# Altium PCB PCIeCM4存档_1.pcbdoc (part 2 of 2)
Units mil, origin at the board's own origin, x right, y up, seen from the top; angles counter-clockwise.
Board outline 9275 x 6345 mil, 4 copper layers (Top Layer, GND, 3V3, Bottom Layer); 98 components, 111 nets, 637 pads, 303 vias.
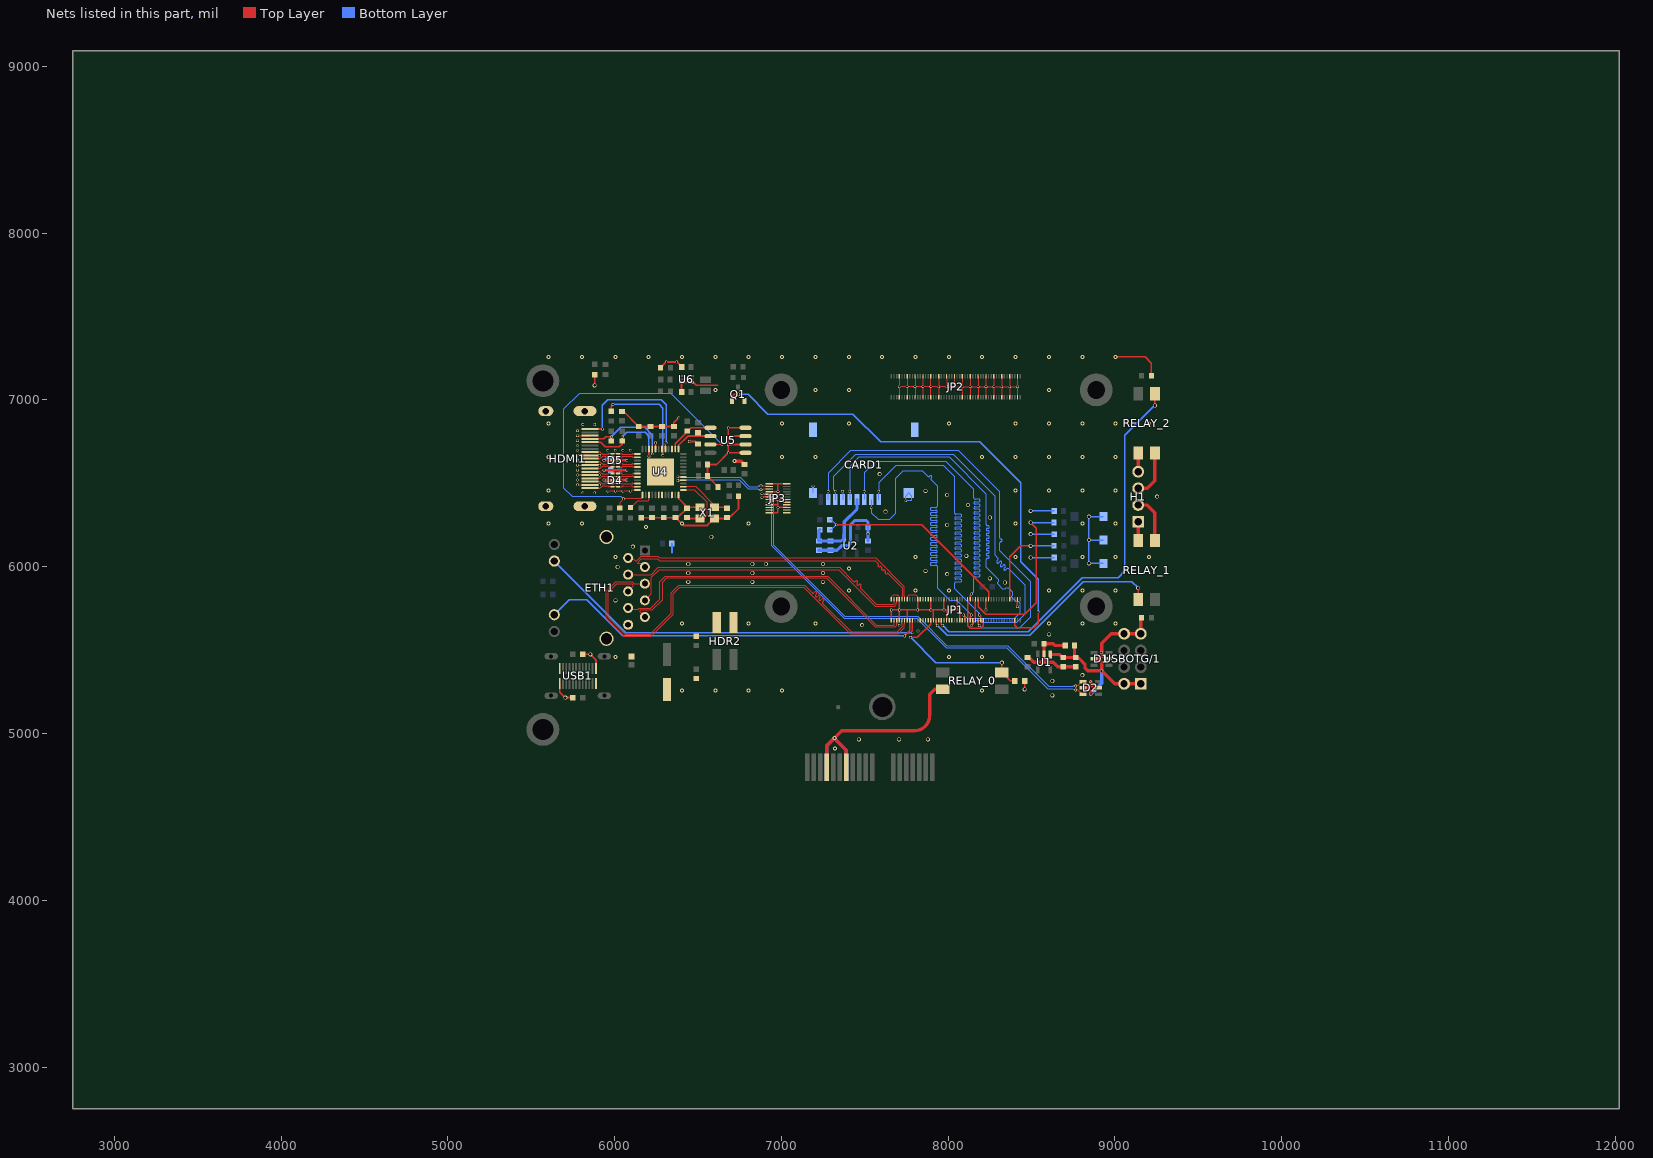
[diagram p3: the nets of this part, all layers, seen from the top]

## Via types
v1: diameter 15.7, hole 11.8, Top Layer to Bottom Layer, 94 vias
v2: diameter 24, hole 12, Top Layer to Bottom Layer, 92 vias
v3: diameter 24, hole 16, Top Layer to Bottom Layer, 67 vias
v4: diameter 15.75, hole 11.81, Top Layer to Bottom Layer, 49 vias
v5: diameter 15.75, hole 11.8, Top Layer to Bottom Layer, 1 vias

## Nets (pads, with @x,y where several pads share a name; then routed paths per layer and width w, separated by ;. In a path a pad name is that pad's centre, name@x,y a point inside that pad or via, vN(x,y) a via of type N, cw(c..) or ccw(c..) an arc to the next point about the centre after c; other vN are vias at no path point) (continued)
GND: BOOT.2 C1.2 C2.1 C3.1 C4.1 C5.1 C6.1 C7.2 C8.1 C9.2 C10.2 C11.1 C12.1 C13.1 C14.1 C15.1 C16.1 C17.1 C18.1 C19.1 C20.1 C21.1 C22.2 C23.1 C24.2 C25.1 C26.1 C27.1 C28.1 C30.1 C31.1 C32.2 C33.2 C34.2 C35.1 CARD1.6 CARD1.10 CARD1.11 CARD1.12 CARD1.13 D1.2 D2.2 D3.2 D4.3 D4.8 D5.3 D5.8 ETH1.P10 ETH1.SHIELD0 ETH1.SHIELD1 HDMI1.2 HDMI1.5 HDMI1.8 HDMI1.11 HDMI1.17 HDMI1.20 HDMI1.21 HDMI1.22 HDMI1.23 HDR2.2 HDR2.4 JP1.15 JP1.18 JP1.21 JP1.24 JP1.29 JP1.34 JP1.39 JP1.44 JP1.47 JP1.50 JP1.51 JP1.54 JP1.57 JP1.61 JP1.66 JP1.71 JP1.76 JP1.80 JP1.83 JP1.87 JP1.99 JP2.2 JP2.5 JP2.8 JP2.11 JP2.14 JP2.17 JP2.20 JP2.23 JP2.32 JP2.35 JP2.38 JP2.41 JP2.44 JP2.47 JP2.54 JP2.57 JP2.60 JP2.63 JP2.66 JP2.69 JP2.72 JP2.75 JP2.78 JP2.81 JP2.84 JP2.87 JP2.90 JP2.93 JP2.96 JP2.99 JP3.1 JP3.6 JP3.7 JP3.11 JP3.12 JP3.17 JP3.23 JP3.24 PWR.1 Q1.2 R3.1 R4.1 R9.1 R12.1 R15.2 R16.1 R18.1 R22.2 R27.1 R28.1 RECOVERY.2 RESET.2 U1.2 U2.2 U4.15 U4.20 U4.36 U4.42 U4.43 U4.46 U4.48 U4.49 U5.1 U5.2 U5.3 U5.4 U6.1 U6.6 USB1.A1 USB1.A12 USB1.B1 USB1.B12 USBOTG/1.7 USBOTG/1.8 X1.2 X1.4 | length 12697.8
  Top Layer w4.9: v4(5777.28,6490.6) HDMI1.2@5852.28,6490.6 ; v4(5777.28,6549.66) HDMI1.5@5852.28,6549.66 ; v4(5777.28,6608.71) HDMI1.8@5852.28,6608.71 ; v4(5777.28,6667.77) HDMI1.11@5852.28,6667.77 ; v4(5777.28,6785.88) HDMI1.17@5852.28,6785.88 ; JP1.51@7659.82,5803.77 7659.82,5820.12 7669.82,5830.12 7697.06,5830.12 7707.06,5820.12 JP1.54@7707.06,5803.77 ; JP1.57@7754.31,5803.77 7754.31,5820.12 7764.31,5830.12 7807.3,5830.12 7817.3,5820.12 JP1.61@7817.3,5803.77
  Top Layer w5.4: v4(5960,6453.08) v1(6095,6453.08) 6101.73,6459.82 U4.36@6137.2,6459.82 ; JP2.47@7707.06,7016.4 JP2.54@7707.06,7142.38 ; v1(7707.06,7079.39) v1(7990.53,7079.39) ; JP2.44@7754.31,7016.4 JP2.57@7754.31,7142.38 ; JP2.41@7801.55,7016.4 JP2.60@7801.55,7142.38 ; JP2.38@7848.79,7016.4 JP2.63@7848.79,7142.38 ; JP2.35@7896.04,7016.4 JP2.66@7896.04,7142.38 ; JP2.32@7943.28,7016.4 JP2.69@7943.28,7142.38 ; JP2.72@7990.53,7142.38 v1(7990.53,7079.39) ; v1(8037.77,7079.39) JP2.75@8037.77,7142.38 ; JP2.23@8085.01,7016.4 JP2.78@8085.01,7142.38 ; JP2.20@8132.26,7016.4 JP2.81@8132.26,7142.38 ; JP2.17@8179.5,7016.4 JP2.84@8179.5,7142.38 ; JP2.14@8226.75,7016.4 JP2.87@8226.75,7142.38 ; JP2.11@8273.99,7016.4 JP2.90@8273.99,7142.38 ; JP2.8@8321.23,7016.4 JP2.93@8321.23,7142.38 ; JP2.5@8368.48,7016.4 JP2.96@8368.48,7142.38 ; JP2.2@8415.72,7016.4 JP2.99@8415.72,7142.38 ; v1(8415.72,7079.39) v1(7990.53,7079.39)
  Top Layer w7.9: v3(5880.74,7087.9) 5880.87,7088.03 PWR.1@5880.87,7151.1 ; JP3.1@6927.65,6323.82 6979.62,6323.82 6979.62,6497.05 ; JP3.7@6927.66,6371.06 6979.62,6371.06 ; JP3.11@6927.65,6402.56 v1(6979.62,6402.56) JP3.12@7031.59,6402.56 ; JP3.17@6927.66,6449.8 v1(6979.66,6449.8) ; JP3.23@6927.65,6497.05 JP3.24@7031.59,6497.05 ; v1(6979.62,6355.32) JP3.6@7031.59,6355.32 ; JP1.50@7659.82,5677.79 v1(7659.82,5740.78) v1(8069.27,5740.6) ; JP1.47@7707.06,5677.79 JP1.54@7707.06,5803.77 ; JP1.44@7754.31,5677.79 7754.31,5740.78 ; v1(7817.3,5740.78) JP1.61@7817.3,5803.77 ; v1(7896.04,5740.78) JP1.66@7896.04,5803.77 ; JP1.34@7911.79,5677.79 7911.79,5740.78 ; v1(7974.78,5740.78) JP1.71@7974.78,5803.77 ; JP1.29@7990.53,5677.79 7990.53,5740.78 ; 8053.52,5740.78 JP1.76@8053.52,5803.77 ; JP1.24@8069.27,5677.79 v1@8069.27,5740.78 ; JP1.21@8116.41,5677.97 8116.41,5646.37 8132.76,5630.02 8194.75,5630.02 8210.9,5646.16 JP1.15@8210.9,5677.97 ; JP1.21@8116.51,5677.79 8116.51,5740.78 JP1.80@8116.51,5803.77 ; JP1.18@8163.75,5677.79 8163.75,5740.78 JP1.83@8163.75,5803.77 ; v1(8226.75,5740.78) JP1.87@8226.75,5803.77 ; v1(8415.72,5760.78) JP1.99@8415.72,5808.77 ; v3(8459.08,5265) R28.1@8459.08,5315 ; v2@9009.35,7258.33 9181.09,7258.33 9219.08,7220.34 R4.1@9219.08,7145
  Top Layer w11: USB1.A12@5671.19,5300.2 5671.19,5248.23 v3(5704.42,5215) R16.1@5749.76,5215 ; R15.2@5809.08,5475 v3(5854.42,5475) 5887.65,5441.77 USB1.B12@5887.65,5389.8 ; C27.1@6045,6930.64 6055,6930.64 C16.1@6145,6840.64 C20.1@6355,6840.64 6355,6863.08 v1(6385,6893.08) ; R22.2@6160,6293.42 6362.9,6293.42 C18.1@6365,6295.52 ; U4.20@6245.47,6705.88 v4(6245.47,6743.08) ; U4.48@6383.27,6430.29 6383.27,6409.68 6435,6357.95 C22.2@6435,6350.64 ; v1(6448.31,6750.61) 6485.03,6750.61 C28.1@6500,6735.64 ; X1.4@6511.69,6356.55 6440.9,6356.55 C22.2@6435,6350.64 ; R18.1@6624.66,6478.08 6622.56,6478.08 C26.1@6557.56,6543.08 C25.1@6557.56,6613.08 6611.68,6613.08 v1(6681.68,6683.08) ; C24.2@6675,6295.52 6669.1,6289.62 X1.2@6598.31,6289.62 ; v1(6681.68,6733.08) U5.2@6785.61,6733.08 ; v1(6681.68,6783.08) U5.3@6785.61,6783.08 ; C23.1@6742.88,6422.77 6742.88,6348.4 6684.1,6289.62 X1.2@6598.31,6289.62 ; U5.1@6785.61,6683.08 v1(6681.68,6683.08) ; U5.4@6785.61,6833.08 v1(6681.68,6833.08) v1(6681.68,6683.08) ; C18.1@6365,6295.52 6379.88,6295.52 C22.2@6435,6350.64 ; C18.1@6365,6295.52 6412.52,6248 6556.69,6248 X1.2@6598.31,6289.62
  Top Layer w11.8: R27.1@6275.34,7193.08 v1(6310.34,7228.08) v1(6372.44,7228.08) C31.1@6402.44,7198.08 ; C30.1@6401.46,7049.06 U6.6@6401.46,7103.4 6473.54,7103.4 6488.85,7088.08 6616.62,7088.08
  Top Layer w15.7: v4(5936.8,6519.98) v4(6073.2,6520.13) ; v4(5936.8,6579.18) v4(6073.2,6579.18) ; v4(5936.8,6638.09) v4(6073.2,6638.24)
  Top Layer w19.3: C5.1@8480,5460.64 8513.54,5427.11 8597.3,5427.11 ; C3.1@8702.44,5528.08 8639.77,5528.08 8629.77,5538.08 8575,5538.08 U1.2@8575,5473.5 8575,5427.11 8630.42,5427.11 8656.83,5400.7 8754.83,5400.7 C4.1@8755,5400.52
  Top Layer w20: v2(6719.42,6632.56) 6759.42,6632.56 C35.1@6779.42,6612.56 ; USBOTG/1.7@9155,5598.08 9155,5690.24 R3.1@9159.76,5695
  Top Layer w20.9: v1(8855,5310.48) 8855,5295.67 8877.59,5273.08 D2.2@8900.24,5273.08 ; D1.2@8965.24,5448.08 8942.59,5448.08 8920,5470.67 v1(8920,5485.48) 8920,5540.23 8977.85,5598.08 USBOTG/1.7@9155,5598.08
  Bottom Layer w5.4: CARD1.10@7189.28,6442.26 CARD1.10@7189.5,6442.48 v1(7189.5,6483.47) ; v1(7744.62,6396.77) 7782.78,6396.77 7782.78,6424.02 CARD1.13@7764.31,6442.48 7744.62,6422.79 v1(7744.62,6396.77)
  Bottom Layer w6.2: CARD1.6@7366.67,6403.11 v1(7366.67,6451.77)
  Bottom Layer w7.9: v3(8494.76,6055) C32.2@8636.86,6055 ; v3(8494.76,6194.99) C34.2@8636.86,6195 ; v3(8494.76,6335) C33.2@8636.86,6335 ; BOOT.2@8930.44,6020 v3(8844.42,6020) v3(8844.42,6160) ; RESET.2@8930.44,6160 v3(8844.42,6160) ; RECOVERY.2@8930.44,6300 v3(8844.42,6300) v3(8844.42,6160)
  Bottom Layer w10: C11.1@6341.98,6140 6344.35,6137.63 6344.35,6083.33
  Bottom Layer w11: v4(5936.8,6519.98) 5947.6,6509.18 C13.1@5977.44,6509.18 ; v4(5936.8,6579.18) C17.1@5977.44,6579.18 ; v4(5936.8,6638.09) 5947.89,6649.18 C12.1@5977.44,6649.18
  Bottom Layer w19.3: C7.2@7224.62,6099.21 7333.35,6099.21 7361.22,6127.08 7400.86,6127.08 7414.62,6140.84 U2.2@7414.62,6172.19 7414.62,6251.77 7439.96,6277.11 7509.28,6277.11 7519.28,6267.11 7519.28,6154.67 C8.1@7519.62,6154.33
  other v1: 7819.42,5615 7706.96,5649.04 7707.06,5740.78 7519.28,6197.53 5810,6443.08 5880,6443.08 6005,6453.08 6050,6453.08 5810,6853.08 5880,6853.08 7754.31,7079.39 7801.55,7079.39 7848.8,7079.39 7896.04,7079.39 7943.28,7079.39 8085.01,7079.39 8132.26,7079.39 8179.5,7079.39 8226.75,7079.39 8273.99,7079.39 8321.23,7079.39 8368.48,7079.39
  other v2: 7322.45,4911.21 6404.4,5258.38 6604.4,5258.38 6804.4,5258.38 7004.4,5258.38 8204.4,5258.38 6004.4,5458.38 8004.4,5458.38 8204.4,5458.38 6404.4,5658.38 6804.4,5658.38 7204.4,5658.38 8604.4,5658.38 8804.4,5658.38 9004.4,5658.38 7404.4,5858.38 7804.4,5858.38 8004.4,5858.38 8604.4,5858.38 8804.4,5858.38 9004.4,5858.38 7406.15,5990.03 6004.4,6058.38 7804.4,6058.38 8404.4,6058.38 8804.4,6058.38 9004.4,6058.38 9204.4,6058.38 6189.4,6238.38 5604.4,6258.38 5804.4,6258.38 6404.4,6258.38 6804.4,6258.38 8404.4,6258.38 8804.4,6258.38 9004.4,6258.38 5604.4,6458.38 8404.4,6458.38 8604.4,6458.38 8804.4,6458.38 9004.4,6458.38 5604.4,6658.38 7004.4,6658.38 7204.4,6658.38 8204.4,6658.38 8404.4,6658.38 8604.4,6658.38 8804.4,6658.38 9004.4,6658.38 5604.4,6858.38 7004.4,6858.38 7404.4,6858.38 8004.4,6858.38 8404.4,6858.38 8604.4,6858.38 8804.4,6858.38 9004.4,6858.38 9204.4,6858.38 6604.4,7058.38 7204.4,7058.38 7404.4,7058.38 8604.4,7058.38 5604.4,7258.38 5804.4,7258.38 6004.4,7258.38 6204.4,7258.38 6404.4,7258.38 6604.4,7258.38 6804.4,7258.38 7004.4,7258.38 7204.4,7258.38 7404.4,7258.38 7604.4,7258.38 7804.4,7258.38 8004.4,7258.38 8204.4,7258.38 8404.4,7258.38 8604.4,7258.38 8804.4,7258.38 9004.4,7258.38
  other v3: 7464.42,4965 7704.81,4965 7877.95,4965 8624.42,5228.84 8624.42,5315 8804.42,5350 8604.42,5595 7484.42,5650 6005.44,5798.28 8339.42,5905 6441.67,5909.05 6825.62,5909.05 7249.42,5909.05 8249.42,5930 7994.42,5955 6441.67,5962.85 6825.62,5962.85 7249.42,5962.85 7864.42,5975 6018.7,5998.28 6441.67,6016.65 6825.62,6016.65 6907.01,6016.65 7249.42,6016.65 8109.42,6065 6109.42,6120 6580,6178.08 7994.42,6250 8249.42,6295 7624.42,6330 8119.42,6370 9253.67,6419.93 7994.42,6430 7864.42,6455 7589.42,6555 7459.42,6600
  other v4: 5909.28,6490.6 5777.28,6519.97 5909.75,6549.66 5777.28,6579.03 5909.69,6608.31 5777.28,6638.08 5909.75,6667.77 5777.28,6697.14 5960,6698.08 6005,6698.08 6050,6698.08 6095,6698.08 5777.28,6726.83 5777.28,6756.2 5777.28,6815.25
GPIO1_A1: JP1.33 RELAY_1.1 | length 1479.1
  Top Layer w7.9: JP1.33@7927.53,5677.79 7927.53,5655.69 v1(7935.4,5647.82) ; RELAY_1.1@9139.42,5802.83 v3(9139.42,5872.83)
  Bottom Layer w7.9: v1(7935.4,5647.82) 7993.22,5590 8489.42,5590 8809.42,5910 9102.25,5910 v3(9139.42,5872.83)
GPIO3_D0: JP1.63
GPIO3_D1: JP1.38
GPIO3_D2: JP1.37
GPIO3_D3: JP1.62
GPIO3_D4: JP1.65
GPIO3_D5: JP1.36
GPIO3_D7: JP1.64
GPIO4_A1: JP1.28
GPIO4_A3: JP1.27
GPIO4_A4: JP1.30
GPIO4_A6: JP1.31 RELAY_2.1 | length 2429.3
  Top Layer w7.9: JP1.31@7959.03,5677.79 7959.03,5655.69 v1(7966.9,5647.82) ; v3(9239.42,6967.17) RELAY_2.1@9239.42,7037.17
  Bottom Layer w7.9: v1(7966.9,5647.82) 8004.72,5610 8479.42,5610 8804.42,5935 9019.42,5935 9059.42,5975 9059.42,6787.17 v3(9239.42,6967.17)
GPIO4_A7: JP1.32
GPIO4_C0: JP1.35 R28.2 RELAY_0.4 | length 944.9
  Top Layer w7.9: v1(7774.42,5576.45) 7815.87,5576.45 7895.62,5656.2 7895.62,5677.66 JP1.35@7895.94,5677.97 ; v3(8321.59,5425) RELAY_0.4@8321.59,5365 8371.59,5315 R28.2@8399.76,5315
  Bottom Layer w7.9: v1(7774.42,5576.45) 7925.87,5425 v3(8321.59,5425)
HDMI_0N-: D5.2 D5.9 HDMI1.9 U4.28 | length 291.2
  Top Layer w4.9: HDMI1.9@5852.28,6628.4 5904.11,6628.4 cw(c5904.11,6605.81) 5920.08,6621.78 ccw(c5936.06,6637.76) 5936.06,6615.16 5936.7,6615.16 ccw(c5950.9,7225.96) 5950.9,6615 5958.51,6615 ccw(c5958.51,6620.78) 5962.59,6616.69 cw(c5966.68,6612.61) 5966.68,6618.38 5987.67,6618.38 6022.33,6618.38 6043.32,6618.38 cw(c6043.32,6612.61) 6047.41,6616.69 ccw(c6051.48,6620.76) 6051.49,6615.01 6101.73,6615.16 ccw(c6101.71,6620.97) 6105.82,6616.86 cw(c6109.92,6612.76) 6109.92,6618.55 U4.28@6137.2,6618.55
HDMI_0P+: D5.1 D5.10 HDMI1.7 U4.29 | length 291.2
  Top Layer w4.9: HDMI1.7@5852.28,6589.03 5904.11,6589.03 ccw(c5904.11,6611.62) 5920.08,6595.65 cw(c5936.06,6579.67) 5936.06,6602.26 5936.7,6602.26 ccw(c5950.9,7213.06) 5950.9,6602.1 5958.51,6602.1 cw(c5958.51,6596.32) 5962.59,6600.41 ccw(c5966.68,6604.49) 5966.68,6598.71 5987.67,6598.71 6022.33,6598.71 6043.32,6598.71 ccw(c6043.32,6604.49) 6047.41,6600.41 cw(c6051.51,6596.3) 6051.49,6602.11 6101.73,6602.26 cw(c6101.75,6596.49) 6105.82,6600.57 ccw(c6109.92,6604.66) 6109.92,6598.87 U4.29@6137.2,6598.87
HDMI_1N-: D4.5 D4.6 HDMI1.6 U4.31 | length 291.2
  Top Layer w4.9: HDMI1.6@5852.28,6569.34 5904.11,6569.34 cw(c5904.11,6546.75) 5920.08,6562.72 ccw(c5936.06,6578.7) 5936.06,6556.1 5936.7,6556.1 ccw(c5950.9,7251.18) 5950.9,6555.96 5958.51,6555.96 ccw(c5958.51,6561.74) 5962.59,6557.65 cw(c5966.68,6553.57) 5966.68,6559.34 5987.67,6559.34 6022.32,6559.34 6038.21,6559.34 cw(c6038.21,6553.57) 6042.3,6557.65 ccw(c6046.37,6561.73) 6046.38,6555.97 6106.83,6556.1 ccw(c6106.82,6561.91) 6110.92,6557.8 cw(c6115.02,6553.71) 6115.02,6559.5 U4.31@6137.2,6559.5
HDMI_1P+: D4.4 D4.7 HDMI1.4 U4.32 | length 291.2
  Top Layer w4.9: HDMI1.4@5852.28,6529.97 5904.11,6529.97 ccw(c5904.11,6552.56) 5920.08,6536.59 cw(c5936.06,6520.61) 5936.06,6543.2 5936.7,6543.2 ccw(c5950.9,7238.28) 5950.9,6543.06 5958.51,6543.06 cw(c5958.51,6537.28) 5962.59,6541.37 ccw(c5966.68,6545.45) 5966.68,6539.67 5987.67,6539.67 6022.33,6539.67 6038.22,6539.67 ccw(c6038.22,6545.45) 6042.31,6541.37 cw(c6046.41,6537.27) 6046.39,6543.07 6106.83,6543.2 cw(c6106.84,6537.43) 6110.92,6541.51 ccw(c6115.02,6545.6) 6115.02,6539.81 U4.32@6137.2,6539.81
HDMI_2N-: D4.2 D4.9 HDMI1.3 U4.34 | length 291.2
  Top Layer w4.9: HDMI1.3@5852.28,6510.29 5904.11,6510.29 cw(c5904.11,6487.7) 5920.08,6503.67 ccw(c5936.06,6519.65) 5936.06,6497.05 5936.7,6497.05 ccw(c5950.9,7107.85) 5950.9,6496.89 5958.51,6496.89 ccw(c5958.51,6502.67) 5962.59,6498.58 cw(c5966.68,6494.5) 5966.68,6500.27 5987.67,6500.27 6022.33,6500.27 6043.32,6500.27 cw(c6043.32,6494.5) 6047.41,6498.58 ccw(c6051.48,6502.65) 6051.49,6496.9 6101.73,6497.04 ccw(c6101.71,6502.86) 6105.82,6498.75 cw(c6109.92,6494.65) 6109.92,6500.44 U4.34@6137.2,6500.44
HDMI_2P+: D4.1 D4.10 HDMI1.1 U4.35 | length 291.2
  Top Layer w4.9: HDMI1.1@5852.28,6470.92 5904.11,6470.92 ccw(c5904.11,6493.51) 5920.08,6477.54 cw(c5936.06,6461.56) 5936.06,6484.15 5936.7,6484.15 ccw(c5950.9,7094.95) 5950.9,6483.99 5958.51,6483.99 cw(c5958.51,6478.21) 5962.59,6482.3 ccw(c5966.68,6486.38) 5966.68,6480.6 5987.67,6480.6 6022.33,6480.6 6043.32,6480.6 ccw(c6043.32,6486.38) 6047.41,6482.3 cw(c6051.51,6478.19) 6051.49,6484 6101.73,6484.14 cw(c6101.75,6478.38) 6105.82,6482.45 ccw(c6109.92,6486.55) 6109.92,6480.76 U4.35@6137.2,6480.76
HDMI_CN-: D5.5 D5.6 HDMI1.12 U4.25 | length 291.2
  Top Layer w4.9: HDMI1.12@5852.28,6687.45 5904.11,6687.45 cw(c5904.11,6664.86) 5920.08,6680.83 ccw(c5936.06,6696.81) 5936.06,6674.21 5936.7,6674.21 ccw(c5950.9,7369.29) 5950.9,6674.07 5958.51,6674.07 ccw(c5958.51,6679.85) 5962.59,6675.76 cw(c5966.68,6671.68) 5966.68,6677.45 5987.67,6677.45 6022.32,6677.45 6043.31,6677.45 cw(c6043.31,6671.68) 6047.4,6675.76 ccw(c6051.47,6679.83) 6051.48,6674.08 6101.73,6674.21 ccw(c6101.71,6680.02) 6105.82,6675.91 cw(c6109.92,6671.82) 6109.92,6677.61 U4.25@6137.2,6677.61
HDMI_CP+: D5.4 D5.7 HDMI1.10 U4.26 | length 291.2
  Top Layer w4.9: HDMI1.10@5852.28,6648.08 5904.11,6648.08 ccw(c5904.11,6670.67) 5920.08,6654.7 cw(c5936.06,6638.72) 5936.06,6661.31 5936.7,6661.31 ccw(c5950.9,7356.39) 5950.9,6661.17 5958.51,6661.17 cw(c5958.51,6655.39) 5962.59,6659.48 ccw(c5966.68,6663.56) 5966.68,6657.78 5987.67,6657.78 6022.33,6657.78 6043.32,6657.78 ccw(c6043.32,6663.56) 6047.41,6659.48 cw(c6051.51,6655.38) 6051.49,6661.18 6101.73,6661.31 cw(c6101.74,6655.54) 6105.82,6659.62 ccw(c6109.92,6663.72) 6109.92,6657.92 U4.26@6137.2,6657.92
HDMIDET: R19.1 U4.18 | length 675.6
  Top Layer w7.9: U4.18@6284.84,6705.88 6284.84,6672.43 v4(6289.63,6667.65)
  Top Layer w11.8: R19.1@5980,6932.74 5980,6962.74 v1(5990,6972.74)
  Bottom Layer w7.9: v1(5990,6972.74) 6266.68,6972.74 6289.63,6949.79 v4(6289.63,6667.65)
HDMIHPD: HDMI1.19 U4.17 | length 891.7
  Top Layer w7.9: U4.17@6304.53,6705.88 6304.53,6737.65 v4(6309.52,6742.65)
  Top Layer w11.8: HDMI1.19@5852.28,6825.25 v4(5927.28,6825.25)
  Bottom Layer w7.9: v4(5927.28,6825.25) 5927.28,6967.87 5959.42,7000 6279.42,7000 6309.52,6969.9 v4(6309.52,6742.65)
HDMISCL: HDMI1.15 R20.2 U4.22 | length 597.8
  Top Layer w7.9: HDMI1.15@5852.28,6746.51 5917.91,6746.51 5944.42,6720 6029.42,6720 6045.01,6735.59 R20.2@6045,6753.42 v4(6045,6778.08) ; v4(6206.12,6662.65) U4.22@6206.1,6705.88
  Bottom Layer w7.9: v4(6045,6778.08) 6071.92,6805 6184.42,6805 6206.12,6783.3 v4(6206.12,6662.65)
HDMISDA: HDMI1.16 R21.2 U4.21 | length 586.1
  Top Layer w7.9: HDMI1.16@5852.28,6766.2 5935.62,6766.2 5947.5,6778.08 v4(5980,6778.08) R21.2@5980,6753.42 ; U4.21@6225.79,6705.88 6225.79,6677.26 v4(6225.86,6677.18)
  Bottom Layer w7.9: v4(5980,6778.08) 6036.92,6835 6179.42,6835 6225.86,6788.56 v4(6225.86,6677.18)
HXIN: C22.1 U4.1 X1.1 | length 373.1
  Top Layer w4.9: U4.1@6412.8,6459.82 6480.42,6459.82 6555,6385.24 6555,6307.93 X1.1@6524.19,6277.12
  Top Layer w11: C22.1@6435,6295.52 6440.9,6289.62 X1.1@6511.69,6289.62
HXOUT: C24.1 U4.2 X1.3 | length 323.3
  Top Layer w4.9: U4.2@6412.8,6479.5 6488.58,6479.5 6598.31,6369.77 X1.3@6598.31,6356.55
  Top Layer w11: X1.3@6598.31,6356.55 6669.1,6356.55 C24.1@6675,6350.64
LED: LED1.1 U4.39 | length 162.6
  Top Layer w5: LED1.1@6092.3,6354.58 6096.5,6354.58 6135,6393.08 6198.59,6393.08 6206.1,6400.6 U4.39@6206.1,6430.29
LED1: ETH1.13 JP1.43 | length 2333.5
  Top Layer w7.9: v1(7739.42,5584.82) 7769.95,5615.35 JP1.43@7769.95,5677.97
  Bottom Layer w7.9: ETH1.13@5638.54,5712.26 5727.91,5801.62 5832.8,5801.62 6049.6,5584.82 v1(7739.42,5584.82)
LED2: ETH1.12 JP1.42 | length 2397.9
  Top Layer w7.9: v1@7785.7,5605 JP1.42@7785.7,5677.97
  Bottom Layer w7.9: ETH1.12@5638.54,6033.91 6067.64,5604.82 v1(7785.7,5604.82)
MDI0+: ETH1.P2 JP1.56 | length 1828.2
  Top Layer w4.9: ETH1.P2@6081.45,6052.18 6085.23,6055.96 6103.56,6055.96 6125.4,6034.12 6130.3,6034.12 6156.01,6059.83 6262.83,6059.83 6272.66,6050 7567.37,6050 7737.03,5880.34 7737.03,5824.06 7738.46,5822.63 JP1.56@7738.46,5803.95
MDI0-: ETH1.P3 JP1.55 | length 1828.3
  Top Layer w4.9: ETH1.P3@6181.45,5998.28 6163.1,6016.64 6142.88,6016.64 6139.42,6020.1 6139.42,6025 6161.35,6046.93 6257.49,6046.93 6267.32,6037.1 7562.03,6037.1 7580.43,6018.7 cw(c7576.75,6015.02) 7580.43,6011.35 ccw(c7584.11,6007.67) 7580.43,6003.99 7583.68,6000.74 ccw(c7587.36,6004.42) 7591.04,6000.74 cw(c7594.71,5997.06) 7598.39,6000.74 7601.64,5997.49 cw(c7597.96,5993.81) 7601.64,5990.13 ccw(c7605.32,5986.46) 7601.64,5982.78 7604.89,5979.53 ccw(c7608.57,5983.2) 7612.25,5979.53 cw(c7615.93,5975.85) 7619.6,5979.53 7622.86,5976.28 cw(c7619.18,5972.6) 7622.86,5968.92 ccw(c7626.53,5965.24) 7622.86,5961.56 7626.11,5958.31 ccw(c7629.78,5961.99) 7633.46,5958.31 cw(c7637.14,5954.64) 7640.82,5958.31 7724.13,5875 7724.13,5824.06 7722.71,5822.63 JP1.55@7722.71,5803.95
MDI1+: ETH1.P4 JP1.52 | length 1775.7
  Top Layer w4.9: ETH1.P4@6081.45,5952.18 6218.36,5952.18 6262.38,5996.2 7348.7,5996.2 7432.38,5912.52 ccw(c7437.69,5917.82) 7442.99,5912.52 7444.64,5914.17 cw(c7449.95,5908.87) 7455.25,5903.56 7453.6,5901.91 ccw(c7458.9,5896.61) 7464.2,5891.31 7465.86,5892.96 cw(c7471.16,5887.65) 7476.46,5882.35 7474.81,5880.7 ccw(c7480.11,5875.4) 7474.81,5870.09 7569.42,5775.48 7673.42,5775.48 7676.88,5778.95 7676.88,5783.85 7675.46,5785.27 JP1.52@7675.46,5803.95
MDI1-: ETH1.P7 JP1.53 | length 1769.7
  Top Layer w4.9: ETH1.P7@6181.45,5798.28 6219.9,5836.73 6219.9,5935.49 6267.72,5983.3 7343.36,5983.3 7564.08,5762.58 7678.76,5762.58 7689.78,5773.6 7689.78,5783.85 7691.21,5785.27 JP1.53@7691.21,5803.95
MDI2+: ETH1.P5 JP1.45 | length 2626.8
  Top Layer w4.9: ETH1.P5@6181.45,5898.28 6178.89,5895.72 6121.94,5895.72 6109.76,5907.9 6004.08,5907.9 5946.52,5850.34 5946.52,5694.66 6059.08,5582.1 6219.76,5582.1 6352.32,5714.66 6352.32,5838.6 6389.42,5875.7 7133.72,5875.7 7412.32,5597.1 7699.47,5597.1 7737.03,5634.66 7737.03,5657.87 7738.46,5659.29 JP1.45@7738.46,5677.97
MDI2-: ETH1.P6 JP1.46 | length 2633.4
  Top Layer w4.9: ETH1.P6@6081.45,5852.18 6110.97,5881.7 6110.97,5888.45 6104.42,5895 6009.42,5895 5959.42,5845 5959.42,5700 6064.42,5595 6214.42,5595 6339.42,5720 6339.42,5843.94 6384.08,5888.6 7139.06,5888.6 7184.58,5843.09 ccw(c7189.88,5848.39) 7195.18,5843.09 7200.45,5848.36 cw(c7205.76,5843.06) 7211.06,5837.75 7205.79,5832.48 ccw(c7211.09,5827.18) 7216.4,5821.87 7221.67,5827.15 cw(c7226.97,5821.84) 7232.27,5816.54 7227,5811.27 ccw(c7232.31,5805.96) 7237.61,5800.66 7242.88,5805.93 cw(c7248.18,5800.63) 7253.49,5795.33 7248.22,5790.05 ccw(c7253.52,5784.75) 7248.21,5779.45 7417.66,5610 7694.13,5610 7724.13,5640 7724.13,5657.87 7722.71,5659.29 JP1.46@7722.71,5677.97
MDI3+: ETH1.P8 JP1.49 | length 1891
  Top Layer w4.9: ETH1.P8@6081.45,5752.18 6089.87,5743.77 6140.87,5743.77 6148.11,5751.01 6217.19,5751.01 6271.52,5805.34 6271.52,5910.34 6303.58,5942.4 7277.36,5942.4 7570.26,5649.5 7673.42,5649.5 7676.88,5652.97 7676.88,5657.87 7675.46,5659.29 JP1.49@7675.46,5677.97
MDI3-: ETH1.P9 JP1.48 | length 1888.2
  Top Layer w4.9: ETH1.P9@6181.45,5698.28 6149.99,5729.75 6149.99,5734.65 6153.46,5738.11 6222.53,5738.11 6284.42,5800 6284.42,5905 6308.92,5929.5 7272.02,5929.5 7564.92,5636.6 7678.76,5636.6 7689.78,5647.62 7689.78,5657.87 7691.21,5659.29 JP1.48@7691.21,5677.97
MS_SCL: R24.1 U4.13 U5.6 | length 255.5
  Top Layer w11: U4.13@6383.27,6705.88 6383.27,6728.08 6438.27,6783.08 U5.6@6574.39,6783.08 ; R24.1@6490.32,6788.75 R24.1@6509.68,6788.75
MS_SDA: R25.1 U4.14 U5.5 | length 282.4
  Top Layer w11: U4.14@6363.58,6705.88 6363.58,6738.08 6458.58,6833.08 U5.5@6574.39,6833.08
PCGND: pad.A4 pad.A7 pad.B4 pad.B7 RELAY_0.2 | length 1659.9
  Top Layer w20: pad.B4@7272.45,4797.08 7272.45,4928.03 v2(7317.45,4973.03) ; pad.B7@7389.45,4797.08 7389.45,4901.03 v2(7317.45,4973.03) ; RELAY_0.2@7967.25,5265 7919.42,5265 7888.92,5234.5 7888.92,5107.6 cw(c7798.92,5107.6) 7798.92,5017.6 7362.02,5017.6 ccw(c7362.02,5017.5) 7361.92,5017.5 v2(7317.45,4973.03)
  Bottom Layer w20: pad.A4@7272.45,4797.08 7272.45,4928.03 v2(7317.45,4973.03) 7389.45,4901.03 pad.A7@7389.45,4797.08
PWR_SW1: H1.4 RELAY_2.3 | length 112.8
  Top Layer w20: H1.4@9139.42,6570 RELAY_2.3@9139.42,6682.83
PWR_SW2: H1.3 RELAY_2.4 | length 286.5
  Top Layer w20: H1.3@9139.42,6470 9194.42,6470 9239.42,6515 RELAY_2.4@9239.42,6682.83
RESETN: JP1.96 R32.1 | length 548.7
  Top Layer w7.9: JP1.96@8368.38,5803.95 8368.38,6058.96 8434.42,6125 v3(8494.76,6125)
  Bottom Layer w7.9: v3(8494.76,6125) R32.1@8634.76,6125
RST_SW1: H1.2 RELAY_1.3 | length 286.5
  Top Layer w20: H1.2@9139.42,6370 9194.42,6370 9239.42,6325 RELAY_1.3@9239.42,6157.17
RST_SW2: H1.1 RELAY_1.4 | length 112.8
  Top Layer w20: RELAY_1.4@9139.42,6157.17 H1.1@9139.42,6270
RX: JP1.25
SDCLK: CARD1.5 JP1.22 | length 2548.8
  Top Layer w7.9: v1(8092.88,5710.42) 8100.76,5702.54 JP1.22@8100.76,5677.79
  Bottom Layer w6.2: CARD1.5@7409.98,6403.11 7409.62,6403.47 v1(7409.62,6451.41) 7409.62,6600.2 7464.42,6655 8008.27,6655 8228.34,6434.93 8228.34,6253.45 ccw(c8235.84,6253.45) 8235.84,6245.95 8239.92,6245.95 cw(c8239.92,6238.45) 8239.92,6230.95 8235.84,6230.95 ccw(c8235.84,6223.45) 8235.84,6215.95 8239.92,6215.95 cw(c8239.92,6208.45) 8239.92,6200.95 8235.84,6200.95 ccw(c8235.84,6193.45) 8235.84,6185.95 8239.92,6185.95 cw(c8239.92,6178.45) 8239.92,6170.95 8235.84,6170.95 ccw(c8235.84,6163.45) 8235.84,6155.95 8239.92,6155.95 cw(c8239.92,6148.45) 8239.92,6140.95 8235.84,6140.95 ccw(c8235.84,6133.45) 8235.84,6125.95 8239.92,6125.95 cw(c8239.92,6118.45) 8239.92,6110.95 8235.84,6110.95 ccw(c8235.84,6103.45) 8235.84,6095.95 8239.92,6095.95 cw(c8239.92,6088.45) 8239.92,6080.95 8235.84,6080.95 ccw(c8235.84,6073.45) 8235.84,6065.95 8239.92,6065.95 cw(c8239.92,6058.45) 8239.92,6050.95 8235.84,6050.95 ccw(c8235.84,6043.45) 8228.34,6043.45 8228.34,5996.08 8303.86,5920.56 8303.86,5914.36 8297.56,5908.06 8297.56,5896.86 8328.78,5865.64 8339.98,5865.64 8346.28,5871.94 8362.48,5871.94 8388.71,5845.71 8388.71,5829.51 8382.41,5823.21 8382.41,5817.01 8409.42,5790 8424.42,5790 8432.66,5781.76 8432.66,5723.24 8399.62,5690.2 8113.1,5690.2 v1(8092.88,5710.42)
SDCMD: CARD1.3 JP1.81 | length 2563
  Top Layer w7.9: JP1.81@8132.16,5803.95 8132.16,5828.42 v1(8140.13,5836.4)
  Bottom Layer w6.2: CARD1.3@7500,6403.08 7496.59,6406.49 v1(7496.59,6451.77) 7496.59,6562.17 7564.42,6630 7989.42,6630 8154.42,6465 8154.42,6412.39 ccw(c8161.92,6412.39) 8161.92,6404.89 8183.92,6404.89 cw(c8183.92,6397.39) 8183.92,6389.89 8161.92,6389.89 ccw(c8161.92,6382.39) 8161.92,6374.89 8183.92,6374.89 cw(c8183.92,6367.39) 8183.92,6359.89 8161.92,6359.89 ccw(c8161.92,6352.39) 8161.92,6344.89 8183.92,6344.89 cw(c8183.92,6337.39) 8183.92,6329.89 8161.92,6329.89 ccw(c8161.92,6322.39) 8161.92,6314.89 8183.92,6314.89 cw(c8183.92,6307.39) 8183.92,6299.89 8161.92,6299.89 ccw(c8161.92,6292.39) 8161.92,6284.89 8183.92,6284.89 cw(c8183.92,6277.39) 8183.92,6269.89 8161.92,6269.89 ccw(c8161.92,6262.39) 8161.92,6254.89 8183.92,6254.89 cw(c8183.92,6247.39) 8183.92,6239.89 8161.92,6239.89 ccw(c8161.92,6232.39) 8161.92,6224.89 8183.92,6224.89 cw(c8183.92,6217.39) 8183.92,6209.89 8161.92,6209.89 ccw(c8161.92,6202.39) 8161.92,6194.89 8183.92,6194.89 cw(c8183.92,6187.39) 8183.92,6179.89 8161.92,6179.89 ccw(c8161.92,6172.39) 8161.92,6164.89 8183.92,6164.89 cw(c8183.92,6157.39) 8183.92,6149.89 8161.92,6149.89 ccw(c8161.92,6142.39) 8161.92,6134.89 8183.92,6134.89 cw(c8183.92,6127.39) 8183.92,6119.89 8161.92,6119.89 ccw(c8161.92,6112.39) 8161.92,6104.89 8183.92,6104.89 cw(c8183.92,6097.39) 8183.92,6089.89 8161.92,6089.89 ccw(c8161.92,6082.39) 8161.92,6074.89 8183.92,6074.89 cw(c8183.92,6067.39) 8183.92,6059.89 8161.92,6059.89 ccw(c8161.92,6052.39) 8161.92,6044.89 8183.92,6044.89 cw(c8183.92,6037.39) 8183.92,6029.89 8161.92,6029.89 ccw(c8161.92,6022.39) 8161.92,6014.89 8183.92,6014.89 cw(c8183.92,6007.39) 8183.92,5999.89 8161.92,5999.89 ccw(c8161.92,5992.39) 8161.92,5984.89 8183.92,5984.89 cw(c8183.92,5977.39) 8183.92,5969.89 8161.92,5969.89 ccw(c8161.92,5962.39) 8161.92,5954.89 8183.92,5954.89 cw(c8183.92,5947.39) 8183.92,5939.89 8161.92,5939.89 ccw(c8161.92,5932.39) 8154.42,5932.39 8154.42,5850.69 v1(8140.13,5836.4)
SDD0: CARD1.7 JP1.19 | length 2544.8
  Top Layer w7.9: v1(8140.13,5647.82) 8147.91,5655.59 JP1.19@8147.91,5677.97
  Bottom Layer w6.2: CARD1.7@7323.36,6403.11 v1(7323.36,6451.77) 7314.42,6460.72 7314.42,6542.1 7447.32,6675 8029.42,6675 8279.22,6425.2 8279.22,6070.77 8298.79,6051.21 cw(c8293.48,6045.91) 8298.79,6040.6 8292.6,6034.42 ccw(c8297.91,6029.12) 8303.21,6023.82 8309.39,6030 cw(c8314.7,6024.69) 8320,6019.39 8313.82,6013.21 ccw(c8319.12,6007.91) 8324.42,6002.6 8330.61,6008.78 cw(c8335.91,6003.48) 8341.21,5998.18 8335.03,5992 ccw(c8340.33,5986.69) 8345.64,5981.39 8351.82,5987.57 cw(c8357.12,5982.27) 8362.43,5987.57 8458.14,5891.85 8458.14,5714.3 8408.84,5665 8204.14,5665 8194.37,5674.77 8162.08,5674.77 8140.13,5652.81 v1(8140.13,5647.82)
SDD1: CARD1.8 JP1.17 | length 2559.1
  Top Layer w7.9: JP1.17@8179.5,5677.79 8179.5,5655.69 v1(8187.37,5647.82)
  Bottom Layer w6.2: CARD1.8@7280.06,6403.11 v1(7280.06,6451.77) 7280.06,6560.64 7414.42,6695 8064.42,6695 8309.42,6450 8309.42,6173.04 ccw(c8316.42,6173.04) 8316.42,6166.04 cw(c8316.42,6159.04) 8323.42,6159.04 8323.42,6158.04 cw(c8316.42,6158.04) 8316.42,6151.04 ccw(c8316.42,6144.04) 8309.42,6144.04 8309.42,6095 8494.42,5910 8494.42,5700 8429.42,5635 8200.19,5635 v1(8187.37,5647.82)
SDD2: CARD1.1 JP1.16 | length 2548.2
  Top Layer w7.9: v1(8187.37,5710.42) 8195.25,5702.54 JP1.16@8195.25,5677.79
  Bottom Layer w6.2: CARD1.1@7583.21,6403.11 v1(7583.21,6451.77) 7583.21,6503.79 7684.42,6605 7974.42,6605 8039.42,6540 8039.42,6321.13 ccw(c8046.92,6321.13) 8046.92,6313.63 8073.92,6313.63 cw(c8073.92,6306.13) 8073.92,6298.63 8046.92,6298.63 ccw(c8046.92,6291.13) 8046.92,6283.63 8073.92,6283.63 cw(c8073.92,6276.13) 8073.92,6268.63 8046.92,6268.63 ccw(c8046.92,6261.13) 8046.92,6253.63 8073.92,6253.63 cw(c8073.92,6246.13) 8073.92,6238.63 8046.92,6238.63 ccw(c8046.92,6231.13) 8046.92,6223.63 8073.92,6223.63 cw(c8073.92,6216.13) 8073.92,6208.63 8046.92,6208.63 ccw(c8046.92,6201.13) 8046.92,6193.63 8073.92,6193.63 cw(c8073.92,6186.13) 8073.92,6178.63 8046.92,6178.63 ccw(c8046.92,6171.13) 8046.92,6163.63 8073.92,6163.63 cw(c8073.92,6156.13) 8073.92,6148.63 8046.92,6148.63 ccw(c8046.92,6141.13) 8046.92,6133.63 8073.92,6133.63 cw(c8073.92,6126.13) 8073.92,6118.63 8046.92,6118.63 ccw(c8046.92,6111.13) 8046.92,6103.63 8073.92,6103.63 cw(c8073.92,6096.13) 8073.92,6088.63 8046.92,6088.63 ccw(c8046.92,6081.13) 8046.92,6073.63 8073.92,6073.63 cw(c8073.92,6066.13) 8073.92,6058.63 8046.92,6058.63 ccw(c8046.92,6051.13) 8046.92,6043.63 8073.92,6043.63 cw(c8073.92,6036.13) 8073.92,6028.63 8046.92,6028.63 ccw(c8046.92,6021.13) 8046.92,6013.63 8073.92,6013.63 cw(c8073.92,6006.13) 8073.92,5998.63 8046.92,5998.63 ccw(c8046.92,5991.13) 8046.92,5983.63 8073.92,5983.63 cw(c8073.92,5976.13) 8073.92,5968.63 8046.92,5968.63 ccw(c8046.92,5961.13) 8046.92,5953.63 8073.92,5953.63 cw(c8073.92,5946.13) 8073.92,5938.63 8046.92,5938.63 ccw(c8046.92,5931.13) 8046.92,5923.63 8073.92,5923.63 cw(c8073.92,5916.13) 8073.92,5908.63 8046.92,5908.63 ccw(c8046.92,5901.13) 8039.42,5901.13 8039.42,5868.37 8187.37,5720.42 v1(8187.37,5710.42)
SDD3: CARD1.2 JP1.20 | length 2565.2
  Top Layer w7.9: JP1.20@8132.16,5677.97 8132.16,5702.44 v1(8140.13,5710.42)
  Bottom Layer w6.2: CARD1.2@7539.9,6403.11 v1(7539.9,6354.45) 7539.9,6324.52 7579.42,6285 7649.42,6285 7684.42,6320 7684.42,6529.4 7730.02,6575 7844.42,6575 7877.61,6541.81 ccw(c7882.91,6547.11) 7888.22,6541.81 7890.11,6543.7 cw(c7895.41,6538.4) 7900.72,6533.1 7898.82,6531.2 ccw(c7904.13,6525.9) 7898.82,6520.6 7934.42,6485 7934.42,6362 cw(c7926.92,6362) 7926.92,6354.5 7899.92,6354.5 ccw(c7899.92,6347) 7899.92,6339.5 7926.92,6339.5 cw(c7926.92,6332) 7926.92,6324.5 7899.92,6324.5 ccw(c7899.92,6317) 7899.92,6309.5 7926.92,6309.5 cw(c7926.92,6302) 7926.92,6294.5 7899.92,6294.5 ccw(c7899.92,6287) 7899.92,6279.5 7926.92,6279.5 cw(c7926.92,6272) 7926.92,6264.5 7899.92,6264.5 ccw(c7899.92,6257) 7899.92,6249.5 7926.92,6249.5 cw(c7926.92,6242) 7926.92,6234.5 7899.92,6234.5 ccw(c7899.92,6227) 7899.92,6219.5 7926.92,6219.5 cw(c7926.92,6212) 7926.92,6204.5 7899.92,6204.5 ccw(c7899.92,6197) 7899.92,6189.5 7926.92,6189.5 cw(c7926.92,6182) 7926.92,6174.5 7899.92,6174.5 ccw(c7899.92,6167) 7899.92,6159.5 7926.92,6159.5 cw(c7926.92,6152) 7926.92,6144.5 7899.92,6144.5 ccw(c7899.92,6137) 7899.92,6129.5 7926.92,6129.5 cw(c7926.92,6122) 7926.92,6114.5 7899.92,6114.5 ccw(c7899.92,6107) 7899.92,6099.5 7926.92,6099.5 cw(c7926.92,6092) 7926.92,6084.5 7899.92,6084.5 ccw(c7899.92,6077) 7899.92,6069.5 7926.92,6069.5 cw(c7926.92,6062) 7926.92,6054.5 7899.92,6054.5 ccw(c7899.92,6047) 7899.92,6039.5 7926.92,6039.5 cw(c7926.92,6032) 7926.92,6024.5 7899.92,6024.5 ccw(c7899.92,6017) 7899.92,6009.5 7926.92,6009.5 cw(c7926.92,6002) 7934.42,6002 7934.42,5875 8009.42,5800 8050.55,5800 v1(8140.13,5710.42)
SDDET: JP1.88 R10.2 R11.1 | length 1230.4
  Top Layer w7.9: v1(7329.62,6251.77) 7840.61,6251.77 8242.39,5850 JP1.88@8242.39,5803.95
  Bottom Layer w5.4: R10.2@7289.28,6221.77 7299.62,6221.77 v1(7329.62,6251.77) 7299.62,6281.77 R11.1@7289.62,6281.77
SW_RECOVERY: JP1.84 R31.1 | length 1076
  Top Layer w7.9: JP1.84@8179.4,5803.95 8179.4,5760 8224.4,5715 8459.42,5715 8529.42,5785 8529.42,6230.34 v3(8494.76,6265)
  Bottom Layer w7.9: v3(8494.76,6265) R31.1@8634.76,6265
TX: JP1.23
USB2_DM0: D2.4 JP3.15 | length 2624.4
  Top Layer w5.4: v1(8765,5285.08) 8777.88,5285.08 8803.28,5310.48 D2.4@8809.76,5310.48
  Top Layer w6.2: v4(6882.65,6438.06) 6888.53,6438.06 6892.35,6434.24 JP3.15@6927.55,6434.24
  Bottom Layer w4.9: 6896.85,6432.62 6922.15,6432.62 6954.42,6400.34 6954.42,6130 7384.42,5700 7819.42,5700 7995.64,5523.78 8360.64,5523.78 8604.89,5279.53 8746.7,5279.53 8752.25,5285.08 v1(8765,5285.08)
  Bottom Layer w6.2: v4(6882.65,6438.06) 6892.05,6438.06 6896.85,6433.26
USB2_DM1: JP3.21 U4.5 | length 614
  Top Layer w4.9: v1(6377.8,6540.58) 6379.82,6538.56 U4.5@6412.8,6538.56
  Top Layer w6.2: v4(6877.65,6485.3) 6888.53,6485.3 6892.35,6481.48 JP3.21@6927.55,6481.48
  Bottom Layer w6.2: v1(6377.8,6540.58) 6391.85,6540.58 6396.6,6535.83 6752.33,6535.83 6807.66,6480.51 6813.86,6480.51 ; 6813.9,6480.55 6858.82,6480.55 6863.58,6485.3 v4(6877.65,6485.3)
USB2_DP0: D2.6 JP3.13 | length 2624.6
  Top Layer w5.4: v1(8765,5261.08) 8777.88,5261.08 8803.28,5235.68 D2.6@8809.76,5235.68
  Top Layer w6.2: v4(6882.62,6414.36) 6888.5,6414.36 6892.62,6418.49 JP3.13@6927.55,6418.49
  Bottom Layer w4.9: 6896.82,6419.72 6916.8,6419.72 6941.52,6395 6941.52,6124.66 7379.08,5687.1 7814.08,5687.1 7990.3,5510.88 8355.3,5510.88 8599.54,5266.63 8746.7,5266.63 8752.25,5261.08 v1(8765,5261.08)
  Bottom Layer w6.2: v4(6882.62,6414.36) 6892.14,6414.36 6896.85,6419.07
USB2_DP1: JP3.19 U4.4 | length 614.1
  Top Layer w4.9: v1(6377.8,6516.88) 6379.78,6518.87 U4.4@6412.8,6518.87
  Top Layer w6.2: v4(6877.62,6461.6) 6888.5,6461.6 6892.63,6465.73 JP3.19@6927.55,6465.73
  Bottom Layer w6.2: v1(6377.8,6516.88) 6391.85,6516.88 6396.6,6521.63 6746.45,6521.63 6801.73,6466.35 6858.79,6466.35 6863.55,6461.6 v4(6877.62,6461.6)
USB3_DM0: JP3.5
USB3_DP0: JP3.3
USB3_SSRXN: JP3.2
USB3_SSRXP: JP3.4
USB3_SSTXN: JP3.10
USB3_SSTXP: JP3.8
VCCOTG: C2.2 C3.2 C4.2 D1.5 D2.5 U1.1 USBOTG/1.1 USBOTG/1.2 | length 1044.8
  Top Layer w19.3: U1.1@8612.4,5473.5 8670.17,5473.5 C2.2@8690,5453.68 ; C2.2@8690,5455.64 C4.2@8765,5455.64 ; C3.2@8757.56,5528.08 8757.56,5463.08 C4.2@8765,5455.64 ; v1@8920,5375.96 8837.12,5375.96 8820,5393.08 8820,5415.18 8784.54,5450.64 8770,5450.64 C4.2@8765,5455.64
  Top Layer w20: USBOTG/1.2@9055,5298.08 USBOTG/1.1@9155,5298.08
  Top Layer w20.9: D2.5@8810.29,5273.08 8832.94,5273.08 8855.53,5250.5 v1(8855.53,5235.68) ; D1.5@8874.76,5448.08 8897.41,5448.08 8920,5425.5 8920,5410.68 8920,5375.96 8997.88,5298.08 USBOTG/1.2@9055,5298.08
  Bottom Layer w20: v1(8855.53,5235.68) 8920,5300.16 v1(8920,5375.68)
VCCSD: C6.2 C7.1 CARD1.4 R10.1 U2.1 | length 490.1
  Bottom Layer w19.3: R10.1@7229.62,6221.77 7224.62,6216.77 C7.1@7224.62,6154.33 7359.36,6154.33 U2.1@7377.22,6172.19 ; U2.1@7377.22,6174.02 7377.22,6269.37 7453.28,6345.43 CARD1.4@7453.28,6403.11
WORK_LED: JP1.3 Q1.1 | length 3056.6
  Top Layer w7.9: Q1.1@6703.14,6992.59 6703.14,7020 6717.27,7034.13 v3(6740.74,7034.13) ; JP1.3@8399.87,5677.97 8399.87,5649.55 8414.42,5635 8514.42,5635 8539.42,5660 v1(8539.42,5730)
  Bottom Layer w7.9: v3(6740.74,7034.13) 6800.29,7034.13 6919.42,6915 7429.42,6915 7594.42,6750 8189.42,6750 8434.42,6505 8434.42,6030 8539.42,5925 v1(8539.42,5730)
WP: R23.1 U4.37 U5.7 | length 2245.4
  Top Layer w4.9: R23.1@6029.72,6351.23 6029.72,6383.72 v1(6053.51,6407.5) 6159.39,6407.5 6166.73,6414.85 6166.73,6434.03 U4.37@6167.99,6435.29 ; U5.7@6574.39,6733.08 v1(6643.7,6733.08)
  Bottom Layer w6.2: v1(6053.51,6407.5) 6037.92,6423.08 5745,6423.08 5693.23,6474.85 5693.23,6943.36 5787.95,7038.08 6338.7,7038.08 v1(6643.7,6733.08)
pads on no net: HDMI1.13 HDMI1.14 JP1.1 JP1.2 JP1.5 JP1.6 JP1.13 JP1.14 JP1.26 JP1.40 JP1.41 JP1.58 JP1.59 JP1.60 JP1.67 JP1.68 JP1.69 JP1.70 JP1.72 JP1.73 JP1.74 JP1.75 JP1.77 JP1.78 JP1.79 JP1.82 JP1.85 JP1.86 JP1.94 JP1.95 JP1.97 JP1.98 JP1.100 JP2.1 JP2.3 JP2.4 JP2.6 JP2.7 JP2.9 JP2.10 JP2.12 JP2.13 JP2.15 JP2.16 JP2.18 JP2.19 JP2.21 JP2.22 JP2.24 JP2.25 JP2.26 JP2.27 JP2.28 JP2.29 JP2.30 JP2.31 JP2.33 JP2.34 JP2.36 JP2.37 JP2.39 JP2.40 JP2.42 JP2.43 JP2.45 JP2.46 JP2.50 JP2.51 JP2.52 JP2.53 JP2.55 JP2.56 JP2.58 JP2.59 JP2.61 JP2.62 JP2.64 JP2.65 JP2.67 JP2.68 JP2.70 JP2.71 JP2.73 JP2.74 JP2.76 JP2.77 JP2.79 JP2.80 JP2.82 JP2.83 JP2.85 JP2.86 JP2.88 JP2.89 JP2.91 JP2.92 JP2.94 JP2.95 JP2.97 JP2.98 JP2.100 JP3.9 JP3.14 JP3.16 JP3.18 JP3.20 JP3.22 U4.9 U4.10 U4.11 U4.12 U4.38 U4.45 USB1.0 USB1.A2 USB1.A3 USB1.A6 USB1.A7 USB1.A8 USB1.A10 USB1.A11 USB1.B2 USB1.B3 USB1.B6 USB1.B7 USB1.B8 USB1.B10 USB1.B11

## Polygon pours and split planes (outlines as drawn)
1V2 on 3V3 (solid, remove dead copper): 6141.3,6678.08 6270,6678.08 6270,6435.68 6141.3,6435.68
GND on Top Layer (solid, remove dead copper, pour order 2): 6916.63,6555.43 7042.62,6555.43 7042.62,6264.76 6916.63,6264.76
GND on GND (solid, remove dead copper): 4104.42,8845 11574.42,8845 11574.42,3000 4104.42,3000
GND on Top Layer (solid, remove dead copper, pour order 8): 6128.35,6714.73 6421.65,6714.73 6421.65,6421.43 6128.35,6421.43
3V3 on 3V3 (solid, remove dead copper): 4090,8693.08 11775,8693.08 11775,4103.08 4090,4103.08
GND on Bottom Layer (solid, remove dead copper, pour order 46): 4445,7673.08 10780,7673.08 10780,4443.08 4445,4443.08
1V2 on 3V3 (solid, remove dead copper): 6141.3,6678.08 6270,6678.08 6270,6435.68 6141.3,6435.68
$6N6824 on Top Layer (solid, remove dead copper, pour order 22): 5961.3,6892.48 6063.8,6892.48 6063.8,6796.58 5961.3,6796.58
GND on Top Layer (solid, remove dead copper, pour order 24): 7600.76,7145.92 8490.53,7145.92 8490.53,7012.85 7600.76,7012.85
5V on Top Layer (solid, remove dead copper, pour order 26): 8254.32,5691.62 8340.22,5691.62 8340.22,5487.43 8254.32,5487.43
GND on Top Layer (solid, remove dead copper, pour order 42): 3000,8838.08 11105,8838.08 11105,3538.08 3000,3538.08
5V on Bottom Layer (solid, remove dead copper, pour order 34): 5699.97,5231.89 5873.87,5231.89 5943.87,5301.89 5943.87,5388.11 5873.87,5458.11 5699.97,5458.11 5689.97,5448.11 5689.97,5241.89
5V on Bottom Layer (solid, remove dead copper, pour order 38): 5898.87,5256.89 6024.42,5256.89 6064.42,5296.89 6064.42,5393.11 6024.42,5433.11 5898.87,5433.11 5878.87,5413.11 5878.87,5276.89
$6N3355 on 3V3 (solid, remove dead copper): 6587.44,6623.08 6462.12,6623.08 6441.86,6606.59 6441.87,6549.29 6461.8,6533.08 6587.44,6533.08 6622.44,6568.08 6622.44,6588.08
$6N3355 on Top Layer (solid, remove dead copper, pour order 16): 6502.44,6623.08 6468.27,6623.08 6412.8,6577.93 6467.95,6533.08 6502.44,6533.08
3V3 on Top Layer (solid, remove dead copper, pour order 28): 6385,7148.08 6395.43,7158.52 6430,7158.52 6430,7226.02 6481.15,7226.02 6481.15,7144.24 6475,7138.08 6465,7148.08
$6N28730 on Top Layer (solid, remove dead copper, pour order 30): 6440,7133.08 6487.04,7133.08 6502.04,7148.08 6580,7148.08 6580,7097.81 6502.04,7097.81 6486.77,7113.08 6440,7113.08
$6N28750 on Top Layer (solid, remove dead copper, pour order 32): 6320,7213.08 6355,7213.08 6355,7173.47 6349.62,7168.08 6345,7168.08 6345,7149.97 6356.15,7138.82 6364.79,7138.82 6380.53,7123.08 6356.15,7098.7 6356.15,7035.53 6317.55,7035.53 6315,7038.08 6315,7208.08
3V3 on Top Layer (solid, remove dead copper, pour order 34): 6440,7178.08 6490,7178.08 6505,7163.08 6555,7163.08 6565,7173.08 6565,7218.08 6555,7228.08 6450,7228.08 6440,7218.08
5V on Top Layer (solid, remove dead copper, pour order 36): 7943.38,5485 8298.36,5485 8400.69,5382.66 8475.13,5382.66 8494.44,5401.98 8494.44,5415 8489.44,5420 8446.49,5420 8429.44,5437.05 8429.44,5550.8 8340.25,5640 8254.44,5640 8219.44,5605 7869.44,5605 7814.44,5550 6291.17,5550 6291.17,5360.82 6850.24,5360.82 6919.42,5430 7888.38,5430
1V2 on Top Layer (solid, remove dead copper, pour order 38): 6176.99,6955.34 6186.99,6965.34 6213.73,6965.34 6255.98,7007.59 6255.98,7144.55 6262.47,7151.04 6293.97,7151.04 6293.97,7031.83 6310.72,7015.08 6429.95,7015.08 6435,7020.13 6435,7063.08 6440,7068.08 6500,7068.08 6510,7078.08 6580,7078.08 6580,7023.08 6515,6958.08 6479.99,6958.08 6452.92,6931.01 6186.65,6931.01 6176.99,6940.68
5V on Top Layer (solid, remove dead copper, pour order 40): 6376.15,5550 6289.42,5550 6172.53,5433.11 6024.42,5433.11 5984.42,5393.11 5984.42,5296.89 6024.42,5256.89 6187.22,5256.89 6376.15,5445.82

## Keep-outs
3V3:
  region: 7130.43,5019.08 7929.41,5019.08 7929.41,4889.28 7130.43,4889.28
Bottom Layer:
  region: 7085,4708.08 7590,4708.08 7590,4623.08 7085,4623.08
  region: 7627.5,4708.08 7947.5,4708.08 7947.5,4623.08 7627.5,4623.08
Board Outline Layer:
  region: 7085,4888.08 7590,4888.08 7590,4628.08 7085,4628.08
  region: 7627.5,4888.08 7947.5,4888.08 7947.5,4628.08 7627.5,4628.08
  region: 6671.5,5100.49 6975.11,5100.49 6975.11,4844.28 6671.5,4844.28
  lines w3: 5390.3,4844.28 5750.3,4844.28 5750.3,5178.08 6651.5,5178.08 cw(c6651.5,5158.08) 6671.5,5158.08 6671.5,4844.28 6975.15,4844.28 6975.15,5100.48 cw(c7052.8,5100.48) 7130.45,5100.48 7130.41,4678.08 ccw(c7150.41,4678.08) 7150.41,4658.08 7550.5,4658.08 ccw(c7550.5,4678.08) 7570.5,4678.08 7570.5,4951.88 cw(c7608,4951.56) 7645.5,4951.88 7645.5,4678.08 ccw(c7665.5,4678.08) 7665.5,4658.08 7909.41,4658.08 ccw(c7909.41,4678.08) 7929.41,4678.08 7929.41,5184.08 9221.17,5184.08 ccw(c9221.17,5284.08) 9321.17,5284.08 9321.2,7094.98 ccw(c9121.2,7094.98) 9121.2,7294.98 5410.3,7294.98 ccw(c5410.3,7274.99) 5390.3,7274.99 5390.3,4844.28

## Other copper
Top Layer:
  region: 7245.42,5078.92 cw(c7245.42,5088.92) 7235.42,5088.92 7235.42,5226.25 cw(c7245.42,5226.25) 7245.42,5236.25 7308.15,5236.25 cw(c7308.15,5226.25) 7309.51,5236.16 cw(c7303.41,5181.51) 7358.4,5181.51 cw(c7303.41,5181.51) 7328.69,5132.68 7356.47,5094.93 cw(c7348.42,5089) 7358.42,5089 cw(c7348.42,5089) 7348.42,5079 cw(c7348.42,5089) 7340.37,5083.07 7304.67,5131.57 cw(c7312.72,5137.5) 7302.72,5137.5 cw(c7312.72,5137.5) 7310.65,5147.28 ccw(c7303.41,5181.51) 7338.4,5181.51 ccw(c7303.41,5181.51) 7307.56,5216.25 7255.42,5216.25 7255.42,5088.92 cw(c7245.42,5088.92)
Bottom Layer:
  region: 7244.42,5238.71 cw(c7244.42,5228.71) 7254.42,5228.71 7254.42,5101.38 7306.56,5101.38 ccw(c7302.41,5136.12) 7337.4,5136.12 ccw(c7302.41,5136.12) 7309.65,5170.35 cw(c7311.72,5180.13) 7301.72,5180.13 cw(c7311.72,5180.13) 7303.67,5186.06 7339.37,5234.56 cw(c7347.42,5228.63) 7347.42,5238.63 cw(c7347.42,5228.63) 7357.42,5228.63 cw(c7347.42,5228.63) 7355.47,5222.7 7327.69,5184.95 cw(c7302.41,5136.12) 7357.4,5136.12 cw(c7302.41,5136.12) 7308.51,5081.47 cw(c7307.15,5091.38) 7307.15,5081.38 7244.42,5081.38 cw(c7244.42,5091.38) 7234.42,5091.38 7234.42,5228.71 cw(c7244.42,5228.71)

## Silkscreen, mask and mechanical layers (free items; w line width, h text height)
Top Silkscreen Layer:
  lines w10: 6862.4,5746.89 ccw(c6980.51,5746.89) 6980.51,5628.78 8909.64,5628.78 ccw(c8909.64,5746.89) 9027.75,5746.89 9027.75,7085.47 ccw(c8909.64,7085.47) 8909.64,7203.58 6980.51,7203.58 ccw(c6980.51,7085.47) 6862.4,7085.47 6862.4,5746.89
  lines w20: 7505.45,5108.14 cw(c7456.32,5158) 7505.88,5207.43 ; 7710.42,5130 ccw(c7752.39,5130) 7743.42,5089 ccw(c7762.63,5176.83) 7792.42,5092 ccw(c7781.74,5122.42) 7811.42,5135 ccw(c7781.64,5122.38) 7788.42,5154 cw(c8008.7,6181.99) 7738.42,5166 cw(c7747,5198.26) 7714.42,5191 cw(c7744.46,5195.26) 7721.42,5215 cw(c7751.48,5189.25) 7743.42,5228 cw(c7761.3,5142.01) 7773.42,5229 cw(c7766.86,5181.91) 7792.42,5222 cw(c7772.66,5191) 7809.42,5191 ; 7170.42,5107.63 7170.42,5299 7798.92,5299 cw(c7798.92,5209) 7888.92,5209 7888.92,5107.6 cw(c7798.92,5107.6) 7798.92,5017.6 7260.42,5017.63 cw(c7260.42,5107.63) 7170.42,5107.63
  text "PWR_SW" at 9089.42,6465 h23.62 r90
  text "RST_SW" at 9089.42,6270 h23.62 r90
  text "TECH OTAKU / SAVE THE WORLD" at 6269.42,5905 h60
  text "GND /  /  / 5V" at 6779.42,5460 h45
Bottom Silkscreen Layer:
  lines w20: 7504.45,5209.49 ccw(c7455.32,5159.63) 7504.88,5110.2 ; 7714.98,5191 cw(c7751.74,5191) 7731.98,5222 cw(c7757.54,5181.91) 7750.98,5229 cw(c7763.09,5142.01) 7780.98,5228 cw(c7772.92,5189.25) 7802.98,5215 cw(c7779.94,5195.26) 7809.98,5191 cw(c7777.4,5198.26) 7785.98,5166 cw(c7515.7,6181.99) 7735.98,5154 ccw(c7742.75,5122.38) 7712.98,5135 ccw(c7742.66,5122.42) 7731.98,5092 ccw(c7761.76,5176.83) 7780.98,5089 ccw(c7772.01,5130) 7813.98,5130 ; 7169.42,5018.63 7169.42,5210 cw(c7259.42,5210) 7259.42,5300 7797.92,5300 cw(c7797.92,5210) 7887.92,5210 7887.92,5108.6 cw(c7797.92,5108.6) 7797.92,5018.6 7169.42,5018.63
Top Solder Mask Layer:
  region: 7085,4883.08 7605,4883.08 7605,4623.08 7085,4623.08
  region: 7615,4883.08 7955,4883.08 7955,4623.08 7615,4623.08
  region: 6671.46,5090.49 6975.07,5090.49 6975.07,4844.28 6671.46,4844.28
Bottom Solder Mask Layer:
  region: 7085,4883.08 7605,4883.08 7605,4623.08 7085,4623.08
  region: 7615,4883.08 7955,4883.08 7955,4623.08 7615,4623.08
  region: 6671.54,5090.48 6975.15,5090.48 6975.15,4844.28 6671.54,4844.28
